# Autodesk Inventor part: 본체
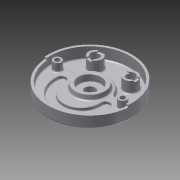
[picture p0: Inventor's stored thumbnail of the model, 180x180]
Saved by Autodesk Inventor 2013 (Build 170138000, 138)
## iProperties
Created: 2015-05
Part Number: 본체
Material: 알루미늄 6061
Document SubType Name: Modeling
Designer: Administrator
Density: 2.71 g/cm^3
Mass: 1085.43 g
Surface Area: 1039.14 cm^2
Volume: 400.527 cm^3
Author: Administrator
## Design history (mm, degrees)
sketch "스케치1"
  geometry: C1 r 95 at (0, 0); 1 further point
  constraints: 1 centre point, 1 coincident
  dimensions: "d0" = 190 diameter of C1
extrude "돌출1" new body sketch "스케치1" distance "d2" = 32; taper "d3" = 0 deg
sketch "스케치2"
  geometry: C1 r 95 at (0, 0) reference; C2 r 90 at (0, 0)
  constraints: 1 centre point, 1 coincident
  dimensions: "d4" = 180 diameter of C2
extrude "돌출2" cut sketch "스케치2" distance "d6" = 18; taper "d7" = 0 deg
sketch "스케치3"
  geometry: L1 (-89.196, 12)-(89.196, 12); L2 (-82.153, -19)-(80.893, -19); L3 (0, 0)-(0, -95); L4 (-82.153, -14)-(80.893, -14); L5 (59, -19)-(59, -14); L6 (41, -19)-(41, -14); L7 (-41, -19)-(-41, -14); L8 (-59, -19)-(-59, -14); A1 r 90 centre (0, 0) between (89.196, 12) and (-89.196, 12); A2 r 59 centre (0, -19) between (-59, -19) and (59, -19); A3 r 41 centre (0, -19) between (-41, -19) and (41, -19); A4 r 9 centre (50, -14) between (59, -14) and (41, -14); A5 r 9 centre (-50, -14) between (-41, -14) and (-59, -14); 3 further points
  constraints: 16 end point, 10 point on circle, 5 centre point, 5 point on line, 3 parallel, 3 symmetric about line, 3 tangent, 2 coincident, 2 perpendicular, 1 horizontal, 1 horizontal alignment, 1 midpoint, 1 vertical alignment, 2 other
  dimensions: "d10" = 90 radius of A1; "d11" = 12 distance from line of L1 point (0, 0); "d13" = 59 radius of A2; "d14" = 41 radius of A3; "d16" = 18 diameter of A4; "d17" = 5 distance of L8.start L8.end; "d18" = 5 distance of L7.start L7.end; "d130" = 19 distance from line of L2 L3.start; "d131" = 5 distance between parallel lines of L4 L2
extrude "돌출3" cut sketch "스케치3" distance "d19" = 7; taper "d20" = 0 deg
sketch "스케치4"
  geometry: L1 (89.196, 12)-(-89.196, 12) reference; A1 r 90 centre (0, 0) between (89.196, 12) and (-89.196, 12) reference; A2 r 42 centre (0, 0) between (40.249, 12) and (-40.249, 12)
  constraints: 2 point on circle, 2 point on line, 1 centre point, 1 coincident
  dimensions: "d21" = 84 diameter of A2
extrude "돌출4" join sketch "스케치4" distance "d23" = 7; taper "d24" = 0 deg
sketch "스케치5"
  geometry: C1 r 35 at (0, 0); A1 r 90 centre (0, 0) between (-89.196, 12) and (89.196, 12) reference
  constraints: 1 centre point, 1 coincident
  dimensions: "d25" = 70 diameter of C1
extrude "돌출5" join sketch "스케치5" distance "d26" = 10; taper "d27" = -10 deg
sketch "스케치6"
  geometry: C1 r 95 at (0, 0) reference; C2 r 25 at (0, 0)
  constraints: 1 centre point, 1 coincident
  dimensions: "d28" = 50 diameter of C2
extrude "돌출6" join sketch "스케치6" distance "d29" = 12; taper "d30" = -15 deg
hole "구멍1" diameter "d33" = 23; stored, may be unused: countersink angle "d37" = 90 deg, drill point angle "d39" = 0 deg; dims "d34" = 6, "d35" = 50, "d36" = 15, "d38" = 15, "d132" = 10, "d133" = 10
sketch "스케치7"
  geometry: L1 (-40.249, 12)-(-89.196, 12) reference; L2 (0, 90)-(0, 0); C1 r 15 at (-40, 52); C2 r 15 at (40, 52); A1 r 42 centre (0, 0) between (40.249, 12) and (-40.249, 12) reference; A2 r 90 centre (0, 0) between (89.196, 12) and (-89.196, 12) reference
  constraints: 2 centre point, 2 end point, 1 perpendicular, 1 point on circle, 1 symmetric about line, 1 other
  dimensions: "d42" = 30 diameter of C1; "d43" = 80 distance of C2.centre C1.centre; "d44" = 52 vertical distance of C2.centre A1.centre
extrude "돌출7" join sketch "스케치7" distance "d45" = 25; taper "d46" = 0 deg
hole "구멍2" diameter "d49" = 20; stored, may be unused: countersink angle "d53" = 90 deg, drill point angle "d55" = 0 deg; dims "d47" = 10, "d48" = 10, "d50" = 6, "d51" = 4, "d52" = 2, "d54" = 15
hole "구멍3" diameter "d58" = 20; stored, may be unused: countersink angle "d62" = 90 deg, drill point angle "d64" = 0 deg; dims "d56" = 10, "d57" = 10, "d59" = 6, "d60" = 4, "d61" = 2, "d63" = 15
sketch "스케치8"
  geometry: L1 (-6, 17.94)-(6, 17.94); L2 (6, 17.94)-(6, -17.94); L3 (6, -17.94)-(-6, -17.94); L4 (-6, -17.94)-(-6, 17.94); C1 r 10 at (0, 0) reference; 3 further points
  constraints: 8 end point, 2 midpoint, 2 parallel, 1 horizontal, 1 horizontal alignment, 1 perpendicular, 1 vertical alignment
  dimensions: "d65" = 12 distance between parallel lines of L2 L4; "d67" = 35.87996 distance between parallel lines of L3 L1
extrude "돌출8" cut sketch "스케치8" distance "d68" = 3; taper "d69" = 0 deg
sketch "스케치9"
  geometry: L1 (-18.483, 6)-(18.483, 6); L2 (18.483, 6)-(18.483, -6); L3 (18.483, -6)-(-18.483, -6); L4 (-18.483, -6)-(-18.483, 6); C1 r 10 at (0, 0) reference; 3 further points
  constraints: 8 end point, 2 midpoint, 2 parallel, 1 horizontal, 1 horizontal alignment, 1 perpendicular, 1 vertical alignment
  dimensions: "d70" = 12 distance between parallel lines of L3 L1; "d72" = 36.96686 distance between parallel lines of L2 L4
extrude "돌출9" cut sketch "스케치9" distance "d73" = 3; taper "d74" = 0 deg
sketch "스케치10"
  geometry: L1 (0, 0)-(0, -90); C1 r 35 at (0, 0) reference; C2 r 95 at (0, 0) reference; C3 r 9 at (-74, 0); C4 r 9 at (74, 0); A1 r 90 centre (0, 0) between (-89.196, 12) and (89.196, 12) reference
  constraints: 2 centre point, 2 end point, 1 horizontal alignment, 1 point on circle, 1 symmetric about line, 1 other
  dimensions: "d75" = 18 diameter of C3; "d76" = 148 distance of C4.centre C3.centre
extrude "돌출10" join sketch "스케치10" distance "d77" = 18; taper "d78" = 0 deg
sketch "스케치11"
  geometry: C1 r 9 at (-74, 0) reference; C2 r 9 at (74, 0) reference; C3 r 9 at (-74, 0) reference; 2 further points
  constraints: 2 coincident
hole "구멍4" sketch "스케치11" at (-74, 0), (74, 0) diameter "d79" = 11; stored, may be unused: countersink angle "d83" = 90 deg, drill point angle "d85" = 0 deg; dims "d80" = 6, "d81" = 18, "d82" = 11, "d84" = 15
sketch "스케치12"
  geometry: L1 (0, 0)-(-89.658, -7.844); L2 (0, 0)-(89.658, -7.844); L3 (-90, 0)-(90, 0); L4 (89.658, -7.844)-(94.638, -8.28); L5 (-89.658, -7.844)-(-94.638, -8.28); A1 r 90 centre (0, 0) between (-90, 0) and (89.196, 12) reference; A2 r 95 centre (0, 0) between (-94.638, -8.28) and (94.638, -8.28) reference; A3 r 90 centre (0, 0) between (-89.196, 12) and (89.196, 12) reference; A4 r 95 centre (0, 0) between (-94.638, -8.28) and (94.638, -8.28); A5 r 90 centre (0, 0) between (89.658, -7.844) and (-89.658, -7.844)
  constraints: 10 end point, 9 point on circle, 2 centre point, 2 coincident, 1 concentric, 1 horizontal, 1 midpoint
  dimensions: "d86" = 180 diameter of A5; "d88" = 5 deg angle of L1 L3; "d90" = 5 deg angle of L2 L3; "d92" = 5 deg angle of L5 L3; "d94" = 5 deg angle of L4 L3
extrude "돌출11" cut sketch "스케치12" distance "d96" = 5; taper "d97" = 0 deg
fillet "모깎기1" dims "d98" = 10
sketch "스케치13"
  geometry: L1 (0, 0)-(0, -72); L2 (0, 0)-(-36.062, -36.062); L3 (0, 0)-(36.062, -36.062); L4 (-36.062, -36.062)-(-50.912, -50.912); L5 (36.062, -36.062)-(50.912, -50.912); C1 r 25 at (0, 0) reference; C2 r 11.5 at (0, 0) reference; A1 r 51 centre (0, 0) between (-36.062, -36.062) and (36.062, -36.062); A2 r 72 centre (0, 0) between (71.48, -8.64) and (-50.912, -50.912); A3 r 72 centre (0, 0) between (50.912, -50.912) and (71.48, -8.64); A4 r 72 centre (0, 0) between (-50.912, -50.912) and (50.912, -50.912); A5 r 51 centre (0, 0) between (36.062, -36.062) and (-36.062, -36.062); 1 further point
  constraints: 12 point on circle, 10 end point, 5 centre point, 2 coincident, 1 symmetric about line, 1 vertical, 2 other
  dimensions: "d100" = 51 radius of A1; "d101" = 72 radius of A2; "d102" = 90 deg angle of L3 L2; "d103" = 21 distance of L3.end L5.end; "d105" = 14.84924 horizontal distance of L2.end L4.end
extrude "돌출12" join sketch "스케치13" distance "d106" = 5; taper "d107" = 0 deg
fillet "모깎기2" dims "d108" = 5
fillet "모깎기3" dims "d109" = 5
node "작업 평면1"
sketch "스케치16"
  geometry: L1 (-37.378, -41.502)-(-45.182, -49.306) reference; L2 (45.182, -49.306)-(37.378, -41.502) reference; A1 r 68 centre (0, 0) between (-45.74, -50.317) and (45.74, -50.317); 5 further points
  constraints: 2 horizontal alignment, 2 point on circle, 1 centre point, 1 coincident, 7 other
  dimensions: "d113" = 136 diameter of A1
feature "엠보싱1" sketch "스케치16" dims "d0" = 190, "d114" = 0.5, "d115" = 0
fillet "모깎기4" dims "d116" = 3
fillet "모깎기5" dims "d117" = 3
fillet "모깎기6" dims "d118" = 3
fillet "모깎기7" dims "d119" = 3
chamfer "모따기1" distance "d120" = 1; stored, may be unused: second distance "d121" = 2, angle "d122" = 45 deg
fillet "모깎기8" dims "d123" = 3
chamfer "모따기2" distance "d124" = 1; stored, may be unused: second distance "d125" = 2, angle "d126" = 45 deg
fillet "모깎기9" dims "d127" = 0.3
fillet "모깎기11" dims "d129" = 5
fillet "모깎기12" dims "d134" = 3
fillet "모깎기13" dims "d135" = 3
node "솔리드1"
node "투영된 루프1"
other parameters: "d112" = -139.25
